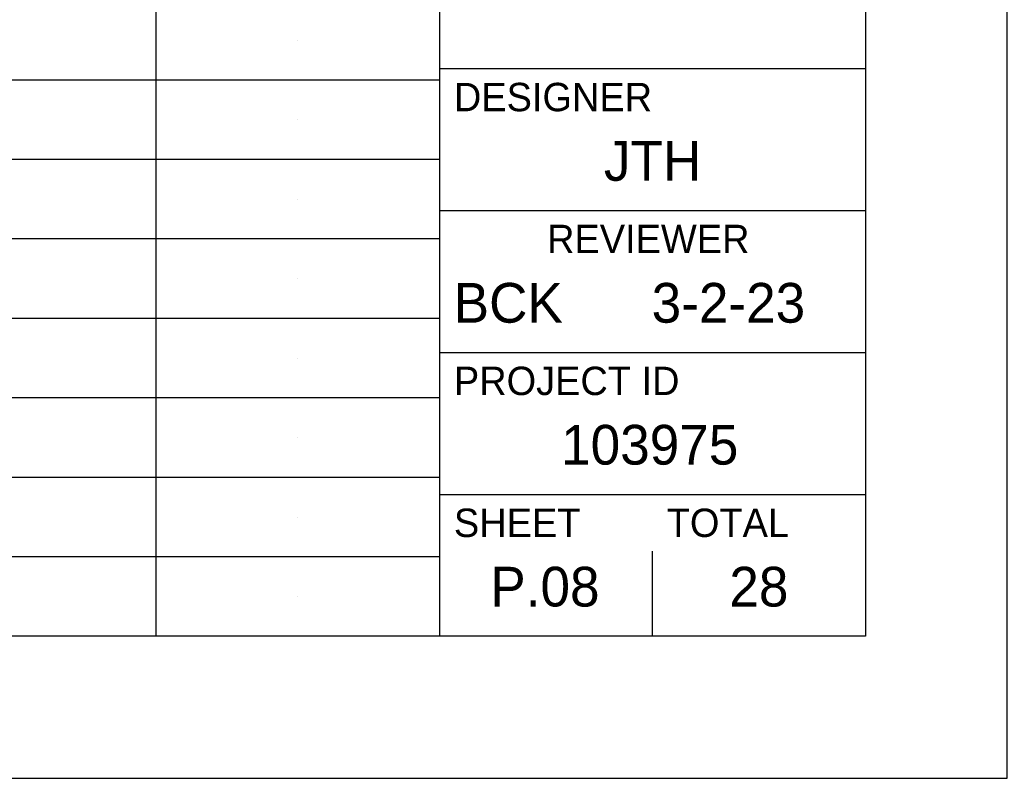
# Model space of a CAD drawing. Extents: x 0 to 34, y 0 to 22.
# Drawn here: x 30.52 to 34, y 0 to 2.672 of the extents above; entities that cross this region are included whole.
import ezdxf

# ---------------------------------------------------------------- set-up
doc = ezdxf.new("R2010")
doc.units = 0
for name, color, linetype in [('SC_Scratch1', 7, 'Continuous'), ('SH_Border', 7, 'Continuous'), ('SH_Cut_Line', 7, 'Continuous'), ('SH_Data', 7, 'Continuous')]:
    doc.layers.add(name, color=color, linetype=linetype)

msp = doc.modelspace()

# ---------------------------------------------------------------- linework, layer by layer
at = {"layer": 'SC_Scratch1'}
for p, q in [((31.5, 2.6), (31.5, 2.6)), ((31.5, 2.32), (31.5, 2.32)), ((31.5, 2.04), (31.5, 2.04)), ((31.5, 1.76), (31.5, 1.76)), ((31.5, 1.48), (31.5, 1.48)), ((31.5, 1.2), (31.5, 1.2)), ((31.5, 0.92), (31.5, 0.92)), ((31.5, 0.64), (31.5, 0.64))]:
    msp.add_line(p, q, dxfattribs=at)
at = {"layer": 'SH_Border'}
for p, q in [((32, 0.5), (32, 21.5)), ((32, 2.5), (33.5, 2.5)), ((32, 2), (33.5, 2)), ((32, 1.5), (33.5, 1.5)), ((32, 1), (33.5, 1))]:
    msp.add_line(p, q, dxfattribs=at)
msp.add_lwpolyline([(1.5, 21.5), (33.5, 21.5), (33.5, 0.5), (1.5, 0.5)], close=True, dxfattribs=at)
at = {"layer": 'SH_Cut_Line'}
msp.add_lwpolyline([(0, 0), (34, 0), (34, 22), (0, 22)], close=True, dxfattribs=at)
at = {"layer": 'SH_Data'}
for p, q in [((31, 21.5), (31, 0.5)), ((32, 2.46), (1.5, 2.46)), ((32, 2.18), (1.5, 2.18)), ((32, 1.9), (1.5, 1.9)), ((32, 1.62), (1.5, 1.62)), ((32, 1.34), (1.5, 1.34)), ((32, 1.06), (1.5, 1.06)), ((32, 0.78), (1.5, 0.78)), ((32.75, 0.5), (32.75, 0.8)), ((32.375, 0.675), (32.375, 0.675))]:
    msp.add_line(p, q, dxfattribs=at)

# ---------------------------------------------------------------- texts
for s, height, p in [('DESIGNER', 0.1, (32.05, 2.35)), ('JTH', 0.14, (32.5786, 2.105)), ('REVIEWER', 0.1, (32.3783, 1.85)), ('BCK', 0.14, (32.0491, 1.605)), ('3-2-23', 0.14, (32.7469, 1.605)), ('PROJECT ID', 0.1, (32.05, 1.35)), ('103975', 0.14, (32.4277, 1.105)), ('SHEET', 0.1, (32.05, 0.85)), ('TOTAL', 0.1, (32.8, 0.85)), ('P.08', 0.14, (32.1782, 0.605)), ('28', 0.14, (33.0206, 0.605))]:
    msp.add_text(s, height=height, dxfattribs=at).set_placement(p)

doc.saveas('drawing.dxf')
